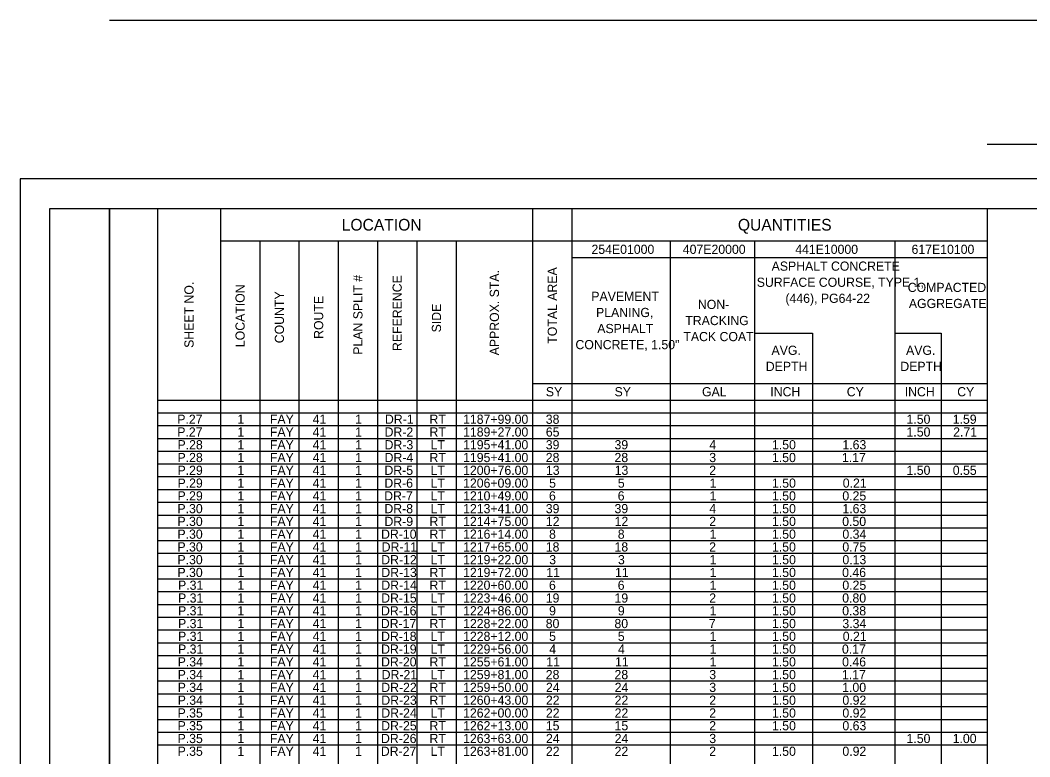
# Model space of a CAD drawing. Extents: x 0 to 34, y 0 to 24.7.
# Drawn here: x 0 to 16.94, y 12.31 to 24.66 of the extents above; entities that cross this region are included whole.
import ezdxf

# ---------------------------------------------------------------- set-up
doc = ezdxf.new("R2010")
doc.units = 0
for name, color, linetype in [('SH_Border', 7, 'Continuous'), ('SH_Cut_Line', 7, 'Continuous'), ('SH_Text', 7, 'Continuous')]:
    doc.layers.add(name, color=color, linetype=linetype)

msp = doc.modelspace()

# ---------------------------------------------------------------- linework, layer by layer
at = {"layer": 'SH_Border'}
for points in [[(0.5, 21.5), (1.5, 21.5), (1.5, 0.5), (0.5, 0.5)], [(1.5, 21.5), (33.5, 21.5), (33.5, 0.5), (1.5, 0.5)]]:
    msp.add_lwpolyline(points, close=True, dxfattribs=at)
at = {"layer": 'SH_Cut_Line'}
msp.add_lwpolyline([(0, 0), (34, 0), (34, 22), (0, 22)], close=True, dxfattribs=at)
at = {"layer": 'SH_Text'}
for p, q in [((1.5, 24.657), (32, 24.657)), ((16.223, 22.58), (17.277, 22.58)), ((2.305, 21.5), (16.223, 21.5)), ((2.305, 21.5), (2.305, 0.566)), ((3.359, 21.5), (3.359, 1.554)), ((8.597, 21.5), (8.597, 1.554)), ((9.256, 21.5), (9.256, 0.566)), ((16.223, 21.5), (16.223, 0.566)), ((3.359, 20.956), (16.223, 20.956)), ((4.018, 20.956), (4.018, 1.554)), ((4.677, 20.956), (4.677, 1.554)), ((5.336, 20.956), (5.336, 1.554)), ((5.995, 20.956), (5.995, 1.554)), ((6.654, 20.956), (6.654, 1.554)), ((7.312, 20.956), (7.312, 1.554)), ((10.903, 20.956), (10.903, 1.554)), ((12.319, 20.956), (12.319, 1.554)), ((14.675, 20.956), (14.675, 1.554)), ((9.256, 20.676), (16.223, 20.676)), ((12.319, 19.408), (13.291, 19.408)), ((13.291, 19.408), (13.291, 1.554)), ((14.675, 19.408), (15.449, 19.408)), ((15.449, 19.408), (15.449, 1.554)), ((8.597, 18.568), (16.223, 18.568)), ((2.305, 18.288), (16.223, 18.288)), ((2.305, 18.074), (16.223, 18.074)), ((2.305, 17.86), (16.223, 17.86)), ((2.305, 17.646), (16.223, 17.646)), ((2.305, 17.432), (16.223, 17.432)), ((2.305, 17.218), (16.223, 17.218)), ((2.305, 17.004), (16.223, 17.004)), ((2.305, 16.789), (16.223, 16.789)), ((2.305, 16.575), (16.223, 16.575)), ((2.305, 16.361), (16.223, 16.361)), ((2.305, 16.147), (16.223, 16.147)), ((2.305, 15.933), (16.223, 15.933)), ((2.305, 15.719), (16.223, 15.719)), ((2.305, 15.505), (16.223, 15.505)), ((2.305, 15.291), (16.223, 15.291)), ((2.305, 15.076), (16.223, 15.076)), ((2.305, 14.862), (16.223, 14.862)), ((2.305, 14.648), (16.223, 14.648)), ((2.305, 14.434), (16.223, 14.434)), ((2.305, 14.22), (16.223, 14.22)), ((2.305, 14.006), (16.223, 14.006)), ((2.305, 13.792), (16.223, 13.792)), ((2.305, 13.578), (16.223, 13.578)), ((2.305, 13.364), (16.223, 13.364)), ((2.305, 13.149), (16.223, 13.149)), ((2.305, 12.935), (16.223, 12.935)), ((2.305, 12.721), (16.223, 12.721)), ((2.305, 12.507), (16.223, 12.507))]:
    msp.add_line(p, q, dxfattribs=at)

# ---------------------------------------------------------------- texts
for s, height, p in [('LOCATION', 0.196, (5.394, 21.13)), ('QUANTITIES', 0.196, (12.04, 21.13)), ('254E01000', 0.154, (9.584, 20.739)), ('407E20000', 0.154, (11.116, 20.739)), ('441E10000', 0.154, (13.002, 20.739)), ('617E10100', 0.154, (14.953, 20.739)), ('ASPHALT CONCRETE ', 0.154, (12.606, 20.457)), ('SURFACE COURSE, TYPE 1, ', 0.154, (12.356, 20.187)), ('COMPACTED ', 0.154, (14.889, 20.1)), ('PAVEMENT ', 0.154, (9.581, 19.95)), ('(446), PG64-22', 0.154, (12.837, 19.918)), ('AGGREGATE', 0.154, (14.908, 19.831)), ('PLANING, ', 0.154, (9.66, 19.68)), ('NON-', 0.154, (11.369, 19.815)), ('TRACKING ', 0.154, (11.158, 19.545)), ('ASPHALT ', 0.154, (9.681, 19.411)), ('TACK COAT', 0.154, (11.126, 19.276)), ('CONCRETE, 1.50"', 0.154, (9.315, 19.141)), ('AVG. ', 0.154, (12.604, 19.046)), ('AVG. ', 0.154, (14.861, 19.046)), ('DEPTH', 0.154, (12.508, 18.776)), ('DEPTH', 0.154, (14.765, 18.776)), ('SY', 0.154, (8.818, 18.351)), ('SY', 0.154, (9.971, 18.351)), ('GAL', 0.154, (11.438, 18.351)), ('INCH', 0.154, (12.583, 18.351)), ('CY', 0.154, (13.866, 18.351)), ('INCH', 0.154, (14.839, 18.351)), ('CY', 0.154, (15.719, 18.351)), ('P.27', 0.154, (2.635, 17.89)), ('1', 0.154, (3.643, 17.89)), ('FAY', 0.154, (4.189, 17.89)), ('41', 0.154, (4.906, 17.89)), ('1', 0.154, (5.62, 17.89)), ('DR-1', 0.154, (6.119, 17.89)), ('RT', 0.154, (6.866, 17.89)), ('1187+99.00', 0.154, (7.43, 17.89)), ('38', 0.154, (8.817, 17.89)), ('1.50', 0.154, (14.869, 17.89)), ('1.59', 0.154, (15.644, 17.89)), ('P.27', 0.154, (2.635, 17.676)), ('1', 0.154, (3.643, 17.676)), ('FAY', 0.154, (4.189, 17.676)), ('41', 0.154, (4.906, 17.676)), ('1', 0.154, (5.62, 17.676)), ('DR-2', 0.154, (6.113, 17.676)), ('RT', 0.154, (6.866, 17.676)), ('1189+27.00', 0.154, (7.43, 17.676)), ('65', 0.154, (8.818, 17.676)), ('1.50', 0.154, (14.869, 17.676)), ('2.71', 0.154, (15.652, 17.676)), ('P.28', 0.154, (2.639, 17.462)), ('1', 0.154, (3.643, 17.462)), ('FAY', 0.154, (4.189, 17.462)), ('41', 0.154, (4.906, 17.462)), ('1', 0.154, (5.62, 17.462)), ('DR-3', 0.154, (6.113, 17.462)), ('LT', 0.154, (6.885, 17.462)), ('1195+41.00', 0.154, (7.43, 17.462)), ('39', 0.154, (8.817, 17.462)), ('39', 0.154, (9.97, 17.462)), ('4', 0.154, (11.56, 17.462)), ('1.50', 0.154, (12.612, 17.462)), ('1.63', 0.154, (13.793, 17.462)), ('P.28', 0.154, (2.639, 17.248)), ('1', 0.154, (3.643, 17.248)), ('FAY', 0.154, (4.189, 17.248)), ('41', 0.154, (4.906, 17.248)), ('1', 0.154, (5.62, 17.248)), ('DR-4', 0.154, (6.113, 17.248)), ('RT', 0.154, (6.866, 17.248)), ('1195+41.00', 0.154, (7.43, 17.248)), ('28', 0.154, (8.817, 17.248)), ('28', 0.154, (9.97, 17.248)), ('3', 0.154, (11.56, 17.248)), ('1.50', 0.154, (12.612, 17.248)), ('1.17', 0.154, (13.786, 17.248)), ('P.29', 0.154, (2.639, 17.034)), ('1', 0.154, (3.643, 17.034)), ('FAY', 0.154, (4.189, 17.034)), ('41', 0.154, (4.906, 17.034)), ('1', 0.154, (5.62, 17.034)), ('DR-5', 0.154, (6.111, 17.034)), ('LT', 0.154, (6.885, 17.034)), ('1200+76.00', 0.154, (7.43, 17.034)), ('13', 0.154, (8.82, 17.034)), ('13', 0.154, (9.973, 17.034)), ('2', 0.154, (11.559, 17.034)), ('1.50', 0.154, (14.869, 17.034)), ('0.55', 0.154, (15.645, 17.034)), ('P.29', 0.154, (2.639, 16.819)), ('1', 0.154, (3.643, 16.819)), ('FAY', 0.154, (4.189, 16.819)), ('41', 0.154, (4.906, 16.819)), ('1', 0.154, (5.62, 16.819)), ('DR-6', 0.154, (6.109, 16.819)), ('LT', 0.154, (6.885, 16.819)), ('1206+09.00', 0.154, (7.43, 16.819)), ('5', 0.154, (8.873, 16.819)), ('5', 0.154, (10.026, 16.819)), ('1', 0.154, (11.566, 16.819)), ('1.50', 0.154, (12.612, 16.819)), ('0.21', 0.154, (13.799, 16.819)), ('P.29', 0.154, (2.639, 16.605)), ('1', 0.154, (3.643, 16.605)), ('FAY', 0.154, (4.189, 16.605)), ('41', 0.154, (4.906, 16.605)), ('1', 0.154, (5.62, 16.605)), ('DR-7', 0.154, (6.106, 16.605)), ('LT', 0.154, (6.885, 16.605)), ('1210+49.00', 0.154, (7.43, 16.605)), ('6', 0.154, (8.871, 16.605)), ('6', 0.154, (10.024, 16.605)), ('1', 0.154, (11.566, 16.605)), ('1.50', 0.154, (12.612, 16.605)), ('0.25', 0.154, (13.792, 16.605)), ('P.30', 0.154, (2.638, 16.391)), ('1', 0.154, (3.643, 16.391)), ('FAY', 0.154, (4.189, 16.391)), ('41', 0.154, (4.906, 16.391)), ('1', 0.154, (5.62, 16.391)), ('DR-8', 0.154, (6.11, 16.391)), ('LT', 0.154, (6.885, 16.391)), ('1213+41.00', 0.154, (7.43, 16.391)), ('39', 0.154, (8.817, 16.391)), ('39', 0.154, (9.97, 16.391)), ('4', 0.154, (11.56, 16.391)), ('1.50', 0.154, (12.612, 16.391)), ('1.63', 0.154, (13.793, 16.391)), ('P.30', 0.154, (2.638, 16.177)), ('1', 0.154, (3.643, 16.177)), ('FAY', 0.154, (4.189, 16.177)), ('41', 0.154, (4.906, 16.177)), ('1', 0.154, (5.62, 16.177)), ('DR-9', 0.154, (6.111, 16.177)), ('RT', 0.154, (6.866, 16.177)), ('1214+75.00', 0.154, (7.43, 16.177)), ('12', 0.154, (8.819, 16.177)), ('12', 0.154, (9.972, 16.177)), ('2', 0.154, (11.559, 16.177)), ('1.50', 0.154, (12.612, 16.177)), ('0.50', 0.154, (13.79, 16.177)), ('P.30', 0.154, (2.638, 15.963)), ('1', 0.154, (3.643, 15.963)), ('FAY', 0.154, (4.189, 15.963)), ('41', 0.154, (4.906, 15.963)), ('1', 0.154, (5.62, 15.963)), ('DR-10', 0.154, (6.054, 15.963)), ('RT', 0.154, (6.866, 15.963)), ('1216+14.00', 0.154, (7.43, 15.963)), ('8', 0.154, (8.872, 15.963)), ('8', 0.154, (10.025, 15.963)), ('1', 0.154, (11.566, 15.963)), ('1.50', 0.154, (12.612, 15.963)), ('0.34', 0.154, (13.793, 15.963)), ('P.30', 0.154, (2.638, 15.749)), ('1', 0.154, (3.643, 15.749)), ('FAY', 0.154, (4.189, 15.749)), ('41', 0.154, (4.906, 15.749)), ('1', 0.154, (5.62, 15.749)), ('DR-11', 0.154, (6.064, 15.749)), ('LT', 0.154, (6.885, 15.749)), ('1217+65.00', 0.154, (7.43, 15.749)), ('18', 0.154, (8.817, 15.749)), ('18', 0.154, (9.97, 15.749)), ('2', 0.154, (11.559, 15.749)), ('1.50', 0.154, (12.612, 15.749)), ('0.75', 0.154, (13.792, 15.749)), ('P.30', 0.154, (2.638, 15.535)), ('1', 0.154, (3.643, 15.535)), ('FAY', 0.154, (4.189, 15.535)), ('41', 0.154, (4.906, 15.535)), ('1', 0.154, (5.62, 15.535)), ('DR-12', 0.154, (6.057, 15.535)), ('LT', 0.154, (6.885, 15.535)), ('1219+22.00', 0.154, (7.43, 15.535)), ('3', 0.154, (8.875, 15.535)), ('3', 0.154, (10.028, 15.535)), ('1', 0.154, (11.566, 15.535)), ('1.50', 0.154, (12.612, 15.535)), ('0.13', 0.154, (13.793, 15.535)), ('P.30', 0.154, (2.638, 15.321)), ('1', 0.154, (3.643, 15.321)), ('FAY', 0.154, (4.189, 15.321)), ('41', 0.154, (4.906, 15.321)), ('1', 0.154, (5.62, 15.321)), ('DR-13', 0.154, (6.058, 15.321)), ('RT', 0.154, (6.866, 15.321)), ('1219+72.00', 0.154, (7.43, 15.321)), ('11', 0.154, (8.826, 15.321)), ('11', 0.154, (9.979, 15.321)), ('1', 0.154, (11.566, 15.321)), ('1.50', 0.154, (12.612, 15.321)), ('0.46', 0.154, (13.789, 15.321)), ('P.31', 0.154, (2.648, 15.107)), ('1', 0.154, (3.643, 15.107)), ('FAY', 0.154, (4.189, 15.107)), ('41', 0.154, (4.906, 15.107)), ('1', 0.154, (5.62, 15.107)), ('DR-14', 0.154, (6.058, 15.107)), ('RT', 0.154, (6.866, 15.107)), ('1220+60.00', 0.154, (7.43, 15.107)), ('6', 0.154, (8.871, 15.107)), ('6', 0.154, (10.024, 15.107)), ('1', 0.154, (11.566, 15.107)), ('1.50', 0.154, (12.612, 15.107)), ('0.25', 0.154, (13.792, 15.107)), ('P.31', 0.154, (2.648, 14.892)), ('1', 0.154, (3.643, 14.892)), ('FAY', 0.154, (4.189, 14.892)), ('41', 0.154, (4.906, 14.892)), ('1', 0.154, (5.62, 14.892)), ('DR-15', 0.154, (6.056, 14.892)), ('LT', 0.154, (6.885, 14.892)), ('1223+46.00', 0.154, (7.43, 14.892)), ('19', 0.154, (8.817, 14.892)), ('19', 0.154, (9.97, 14.892)), ('2', 0.154, (11.559, 14.892)), ('1.50', 0.154, (12.612, 14.892)), ('0.80', 0.154, (13.79, 14.892)), ('P.31', 0.154, (2.648, 14.678)), ('1', 0.154, (3.643, 14.678)), ('FAY', 0.154, (4.189, 14.678)), ('41', 0.154, (4.906, 14.678)), ('1', 0.154, (5.62, 14.678)), ('DR-16', 0.154, (6.053, 14.678)), ('LT', 0.154, (6.885, 14.678)), ('1224+86.00', 0.154, (7.43, 14.678)), ('9', 0.154, (8.873, 14.678)), ('9', 0.154, (10.026, 14.678)), ('1', 0.154, (11.566, 14.678)), ('1.50', 0.154, (12.612, 14.678)), ('0.38', 0.154, (13.79, 14.678)), ('P.31', 0.154, (2.648, 14.464)), ('1', 0.154, (3.643, 14.464)), ('FAY', 0.154, (4.189, 14.464)), ('41', 0.154, (4.906, 14.464)), ('1', 0.154, (5.62, 14.464)), ('DR-17', 0.154, (6.05, 14.464)), ('RT', 0.154, (6.866, 14.464)), ('1228+22.00', 0.154, (7.43, 14.464)), ('80', 0.154, (8.816, 14.464)), ('80', 0.154, (9.969, 14.464)), ('7', 0.154, (11.553, 14.464)), ('1.50', 0.154, (12.612, 14.464)), ('3.34', 0.154, (13.793, 14.464)), ('P.31', 0.154, (2.648, 14.25)), ('1', 0.154, (3.643, 14.25)), ('FAY', 0.154, (4.189, 14.25)), ('41', 0.154, (4.906, 14.25)), ('1', 0.154, (5.62, 14.25)), ('DR-18', 0.154, (6.054, 14.25)), ('LT', 0.154, (6.885, 14.25)), ('1228+12.00', 0.154, (7.43, 14.25)), ('5', 0.154, (8.873, 14.25)), ('5', 0.154, (10.026, 14.25)), ('1', 0.154, (11.566, 14.25)), ('1.50', 0.154, (12.612, 14.25)), ('0.21', 0.154, (13.799, 14.25)), ('P.31', 0.154, (2.648, 14.036)), ('1', 0.154, (3.643, 14.036)), ('FAY', 0.154, (4.189, 14.036)), ('41', 0.154, (4.906, 14.036)), ('1', 0.154, (5.62, 14.036)), ('DR-19', 0.154, (6.055, 14.036)), ('LT', 0.154, (6.885, 14.036)), ('1229+56.00', 0.154, (7.43, 14.036)), ('4', 0.154, (8.875, 14.036)), ('4', 0.154, (10.028, 14.036)), ('1', 0.154, (11.566, 14.036)), ('1.50', 0.154, (12.612, 14.036)), ('0.17', 0.154, (13.786, 14.036)), ('P.34', 0.154, (2.642, 13.822)), ('1', 0.154, (3.643, 13.822)), ('FAY', 0.154, (4.189, 13.822)), ('41', 0.154, (4.906, 13.822)), ('1', 0.154, (5.62, 13.822)), ('DR-20', 0.154, (6.054, 13.822)), ('RT', 0.154, (6.866, 13.822)), ('1255+61.00', 0.154, (7.43, 13.822)), ('11', 0.154, (8.826, 13.822)), ('11', 0.154, (9.979, 13.822)), ('1', 0.154, (11.566, 13.822)), ('1.50', 0.154, (12.612, 13.822)), ('0.46', 0.154, (13.789, 13.822)), ('P.34', 0.154, (2.642, 13.608)), ('1', 0.154, (3.643, 13.608)), ('FAY', 0.154, (4.189, 13.608)), ('41', 0.154, (4.906, 13.608)), ('1', 0.154, (5.62, 13.608)), ('DR-21', 0.154, (6.064, 13.608)), ('LT', 0.154, (6.885, 13.608)), ('1259+81.00', 0.154, (7.43, 13.608)), ('28', 0.154, (8.817, 13.608)), ('28', 0.154, (9.97, 13.608)), ('3', 0.154, (11.56, 13.608)), ('1.50', 0.154, (12.612, 13.608)), ('1.17', 0.154, (13.786, 13.608)), ('P.34', 0.154, (2.642, 13.394)), ('DR-22', 0.154, (6.057, 13.394)), ('1259+50.00', 0.154, (7.43, 13.394)), ('24', 0.154, (8.82, 13.394)), ('24', 0.154, (9.973, 13.394)), ('3', 0.154, (11.56, 13.394)), ('1.50', 0.154, (12.612, 13.394)), ('1.00', 0.154, (13.79, 13.394)), ('1', 0.154, (3.643, 13.394)), ('FAY', 0.154, (4.189, 13.394)), ('41', 0.154, (4.906, 13.394)), ('1', 0.154, (5.62, 13.394)), ('RT', 0.154, (6.866, 13.394)), ('P.34', 0.154, (2.642, 13.179)), ('1', 0.154, (3.643, 13.179)), ('FAY', 0.154, (4.189, 13.179)), ('41', 0.154, (4.906, 13.179)), ('1', 0.154, (5.62, 13.179)), ('DR-23', 0.154, (6.058, 13.179)), ('RT', 0.154, (6.866, 13.179)), ('1260+43.00', 0.154, (7.43, 13.179)), ('22', 0.154, (8.819, 13.179)), ('22', 0.154, (9.972, 13.179)), ('2', 0.154, (11.559, 13.179)), ('1.50', 0.154, (12.612, 13.179)), ('0.92', 0.154, (13.793, 13.179)), ('P.35', 0.154, (2.64, 12.965)), ('1', 0.154, (3.643, 12.965)), ('FAY', 0.154, (4.189, 12.965)), ('41', 0.154, (4.906, 12.965)), ('1', 0.154, (5.62, 12.965)), ('DR-24', 0.154, (6.058, 12.965)), ('LT', 0.154, (6.885, 12.965)), ('1262+00.00', 0.154, (7.43, 12.965)), ('22', 0.154, (8.819, 12.965)), ('22', 0.154, (9.972, 12.965)), ('2', 0.154, (11.559, 12.965)), ('1.50', 0.154, (12.612, 12.965)), ('0.92', 0.154, (13.793, 12.965)), ('P.35', 0.154, (2.64, 12.751)), ('1', 0.154, (3.643, 12.751)), ('FAY', 0.154, (4.189, 12.751)), ('41', 0.154, (4.906, 12.751)), ('1', 0.154, (5.62, 12.751)), ('DR-25', 0.154, (6.056, 12.751)), ('RT', 0.154, (6.866, 12.751)), ('1262+13.00', 0.154, (7.43, 12.751)), ('15', 0.154, (8.818, 12.751)), ('15', 0.154, (9.971, 12.751)), ('2', 0.154, (11.559, 12.751)), ('1.50', 0.154, (12.612, 12.751)), ('0.63', 0.154, (13.793, 12.751)), ('P.35', 0.154, (2.64, 12.537)), ('1', 0.154, (3.643, 12.537)), ('FAY', 0.154, (4.189, 12.537)), ('41', 0.154, (4.906, 12.537)), ('1', 0.154, (5.62, 12.537)), ('DR-26', 0.154, (6.053, 12.537)), ('RT', 0.154, (6.866, 12.537)), ('1263+63.00', 0.154, (7.43, 12.537)), ('24', 0.154, (8.82, 12.537)), ('24', 0.154, (9.973, 12.537)), ('3', 0.154, (11.56, 12.537)), ('1.50', 0.154, (14.869, 12.537)), ('1.00', 0.154, (15.643, 12.537)), ('P.35', 0.154, (2.64, 12.323)), ('1', 0.154, (3.643, 12.323)), ('FAY', 0.154, (4.189, 12.323)), ('41', 0.154, (4.906, 12.323)), ('1', 0.154, (5.62, 12.323)), ('DR-27', 0.154, (6.05, 12.323)), ('LT', 0.154, (6.885, 12.323)), ('1263+81.00', 0.154, (7.43, 12.323)), ('22', 0.154, (8.819, 12.323)), ('22', 0.154, (9.972, 12.323)), ('2', 0.154, (11.559, 12.323)), ('1.50', 0.154, (12.612, 12.323)), ('0.92', 0.154, (13.793, 12.323))]:
    msp.add_text(s, height=height, dxfattribs=at).set_placement(p)
for s, p in [('TOTAL AREA', (9.003, 19.233)), ('PLAN SPLIT #', (5.742, 19.048)), ('REFERENCE', (6.401, 19.111)), ('APPROX. STA.', (8.032, 19.038)), ('SHEET NO.', (2.909, 19.163)), ('LOCATION', (3.766, 19.175)), ('COUNTY', (4.425, 19.241)), ('ROUTE', (5.083, 19.314)), ('SIDE', (7.06, 19.423))]:
    msp.add_text(s, height=0.154, rotation=90, dxfattribs=at).set_placement(p)

doc.saveas('drawing.dxf')
